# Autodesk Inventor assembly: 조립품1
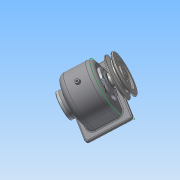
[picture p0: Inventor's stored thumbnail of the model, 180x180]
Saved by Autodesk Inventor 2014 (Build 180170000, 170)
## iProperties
Created: 2015-09
Part Number: 조립품1
Document SubType Name: Assembly
Designer: net
Author: net
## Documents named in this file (14)
- C:\Users\net\Desktop\450907v1029\조립품1.iam
- C:\Users\net\Desktop\450907v1029\부품 본체.ipt
- C:\Users\net\Desktop\450907v1029\뒤커버.ipt
- C:\Users\net\Desktop\450907v1029\볼트 M3 x 8.ipt
- C:\Users\net\Desktop\450907v1029\앞커버.ipt
- C:\Users\net\Desktop\450907v1029\볼트 M3 x 10.ipt
- C:\Users\net\Desktop\450907v1029\베어링 6203.ipt
- C:\Users\net\Desktop\450907v1029\축.ipt
- C:\Users\net\Desktop\450907v1029\키 - 6 x 6 x 22.ipt
- C:\Users\net\Desktop\450907v1029\스퍼기어.ipt
- C:\Users\net\Desktop\450907v1029\오일 실 17 32 8.ipt
- C:\Users\net\Desktop\450907v1029\키 - 5 x 5 x 18.ipt
- C:\Users\net\Desktop\450907v1029\V-벨트풀리.ipt
- C:\Users\net\Desktop\450907v1029\멈춤나사 - M4x10.ipt
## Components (9 placed, 3 different names)
1. V-벨트풀리:1 — 각도:4
2. ISO 4762 M3 x 8:1
3. ISO 4762 M3 x 8:2
4. ISO 4762 M3 x 8:3
5. ISO 4762 M3 x 8:4
6. ISO 4762 M3 x 10:1
7. ISO 4762 M3 x 10:2
8. ISO 4762 M3 x 10:3
9. ISO 4762 M3 x 10:4
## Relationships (1: Angle 1)
- 각도:4 [Angle]: V-벨트풀리:1
